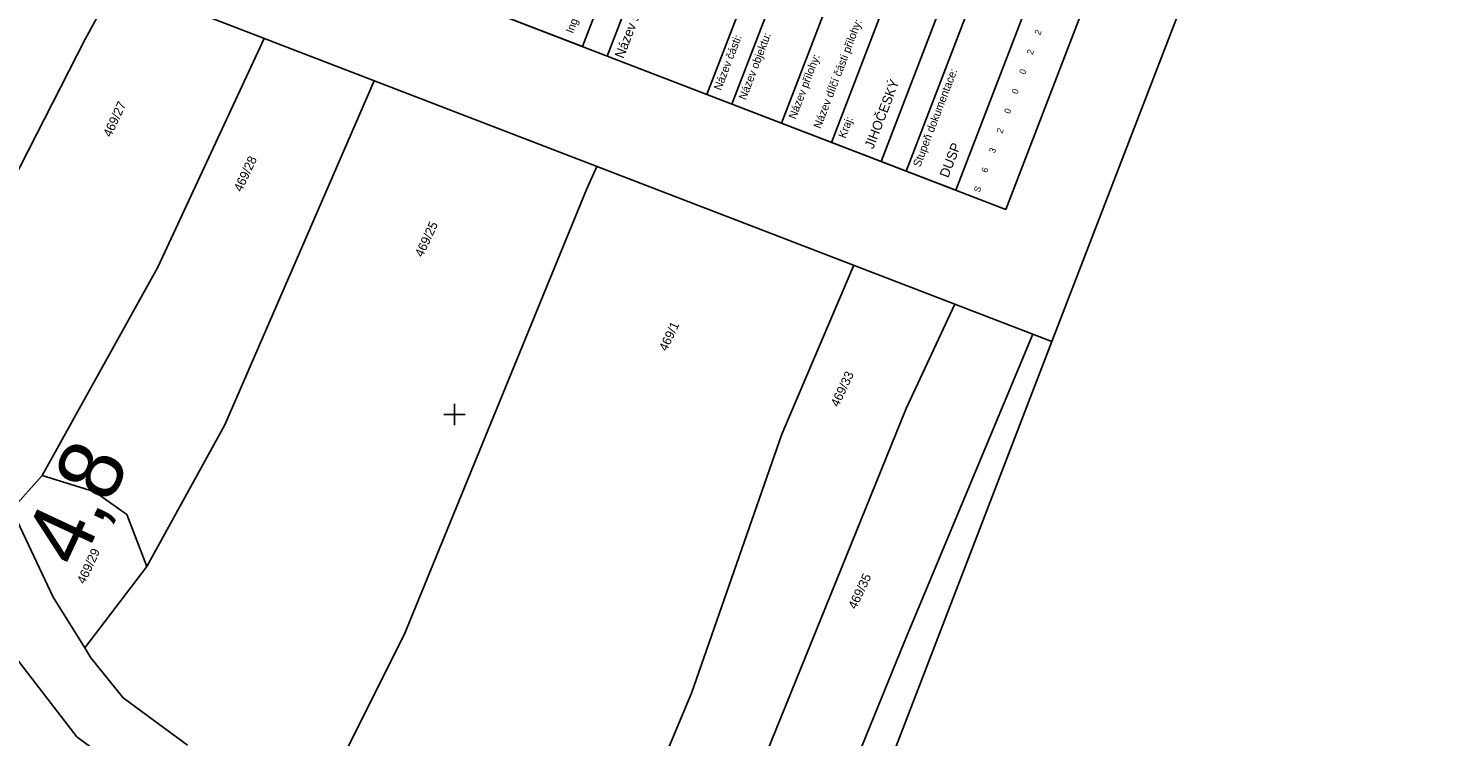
# Model space of a CAD drawing. Extents: x -755344 to -754413, y -1162670 to -1161477.
# Drawn here: x -754679.8 to -754412.6, y -1161960.4 to -1161827.7 of the extents above; entities that cross this region are included whole.
import ezdxf

# ---------------------------------------------------------------- set-up
doc = ezdxf.new("R2010")
doc.units = 0
for name, color, linetype in [('Formát', 7, 'Continuous'), ('Katastrální hranice', 7, 'Continuous'), ('Popisove_pole', 7, 'Continuous'), ('SO 11-10-01_popisove_pole', 7, 'Continuous'), ('Staniceni a namezniky', 7, 'Continuous'), ('Síť', 7, 'Continuous'), ('Vrstva 55', 7, 'Continuous'), ('Vrstva 57', 7, 'Continuous')]:
    doc.layers.add(name, color=color, linetype=linetype)

msp = doc.modelspace()

# ---------------------------------------------------------------- linework, layer by layer
at = {"layer": 'Formát'}
msp.add_line((-754488.01, -1161886.37), (-754412.58, -1161690.39), dxfattribs=at)
msp.add_lwpolyline([(-754488.01, -1161886.37), (-754789.71, -1162670.32), (-755344.08, -1162456.97), (-755042.37, -1161673.02)], close=True, dxfattribs=at)
for points in [[(-755344.08, -1162456.97), (-754789.71, -1162670.32), (-754488.01, -1161886.37), (-755042.37, -1161673.02)], [(-755344.08, -1162456.97), (-754789.71, -1162670.32), (-754488.01, -1161886.37), (-755042.37, -1161673.02)], [(-754789.71, -1162670.32), (-754488.01, -1161886.37), (-755042.37, -1161673.02), (-755344.08, -1162456.97)]]:
    msp.add_lwpolyline(points, dxfattribs=at)
at = {"layer": 'Katastrální hranice'}
msp.add_line((-754682.93, -1161917.84), (-754675.16, -1161934.28), dxfattribs=at)
at = {"layer": 'SO 11-10-01_popisove_pole'}
for p, q in [((-754552.69, -1161840.05), (-754505.87, -1161718.4)), ((-754548.02, -1161841.85), (-754501.2, -1161720.2)), ((-754538.69, -1161845.44), (-754491.87, -1161723.79)), ((-754529.35, -1161849.03), (-754482.54, -1161727.38)), ((-754520.02, -1161852.62), (-754473.2, -1161730.97)), ((-754515.36, -1161854.42), (-754468.54, -1161732.77))]:
    msp.add_line(p, q, dxfattribs=at)
for points in [[(-754739.34, -1161768.22), (-754678.28, -1161609.56), (-754435.63, -1161702.95), (-754496.69, -1161861.6)], [(-754622.68, -1161813.11), (-754561.62, -1161654.46), (-754514.96, -1161672.42), (-754576.02, -1161831.07)], [(-754571.36, -1161832.88), (-754510.3, -1161674.22), (-754444.97, -1161699.37), (-754506.03, -1161858.02)]]:
    msp.add_lwpolyline(points, close=True, dxfattribs=at)
at = {"layer": 'Síť'}
for points in [[(-754600, -1161898), (-754600, -1161900), (-754600, -1161902)], [(-754598, -1161900), (-754600, -1161900), (-754602, -1161900)]]:
    msp.add_lwpolyline(points, dxfattribs=at)
at = {"layer": 'Vrstva 55'}
for p, q in [((-754682.93, -1161917.84), (-754677.24, -1161911.45)), ((-754682.93, -1161917.84), (-754675.16, -1161934.28)), ((-754682.93, -1161917.84), (-754675.16, -1161934.28)), ((-754657.61, -1161928.54), (-754669.27, -1161943.74)), ((-754675.16, -1161934.28), (-754669.27, -1161943.74)), ((-754675.16, -1161934.28), (-754669.27, -1161943.74))]:
    msp.add_line(p, q, dxfattribs=at)
for points in [[(-754700.13, -1161883.31), (-754693.64, -1161874.43), (-754682.9, -1161856.46), (-754669.27, -1161829.84), (-754663.3, -1161818.91)], [(-754677.24, -1161911.45), (-754655.58, -1161872.43), (-754635.62, -1161829.56)], [(-754615.06, -1161837.48), (-754643, -1161901.95), (-754657.61, -1161928.54)], [(-754573.32, -1161853.54), (-754575.25, -1161857.88), (-754609.39, -1161941.34), (-754620.82, -1161964.09), (-754630.9, -1161973.72)], [(-754581.59, -1162005.57), (-754574.99, -1161995.43), (-754567.68, -1161981.15), (-754555.59, -1161952.23), (-754538.63, -1161903.69), (-754525.17, -1161872.07)], [(-754566.03, -1162015.68), (-754549.09, -1161982.12), (-754515.32, -1161898.89), (-754506.22, -1161879.36)], [(-754548.91, -1162026.6), (-754544.92, -1162019.1), (-754539.09, -1162000.11), (-754515.76, -1161942.9), (-754491.63, -1161884.98)], [(-754677.24, -1161911.45), (-754667.41, -1161914.5), (-754661.4, -1161918.76), (-754657.61, -1161928.54)], [(-754637.39, -1161984.8), (-754642.71, -1161981.11), (-754670.75, -1161960.4), (-754682.08, -1161945.77), (-754686.04, -1161937.95)], [(-754669.27, -1161943.74), (-754668.12, -1161945.6), (-754662.1, -1161953.11), (-754649.99, -1161962)], [(-754669.27, -1161943.74), (-754668.12, -1161945.6), (-754662.1, -1161953.11), (-754649.99, -1161962)]]:
    msp.add_lwpolyline(points, dxfattribs=at)

# ---------------------------------------------------------------- texts
at = {"layer": 'Popisove_pole'}
for s, p in [('2', (-754490.24, -1161829.04)), ('2', (-754491.66, -1161832.72)), ('0', (-754493.08, -1161836.41)), ('0', (-754494.5, -1161840.09)), ('0', (-754495.92, -1161843.78)), ('2', (-754497.34, -1161847.47)), ('3', (-754498.76, -1161851.15)), ('6', (-754500.18, -1161854.84)), ('S', (-754501.59, -1161858.53))]:
    msp.add_text(s, height=1.2, rotation=68.9507, dxfattribs=at).set_placement(p)
at = {"layer": 'SO 11-10-01_popisove_pole'}
for s, height, p in [('Ing. Vít Hoznour', 1.5, (-754577.79, -1161828.73)), ('Název stavby/akce:', 1.8, (-754568.33, -1161833.44)), ('Název dílčí části přílohy:', 1.5, (-754531.39, -1161846.59)), ('Název části:', 1.5, (-754550.05, -1161839.41)), ('Název objektu:', 1.5, (-754545.39, -1161841.2)), ('Název přílohy:', 1.5, (-754536.05, -1161844.8)), ('JIHOČESKÝ', 1.8, (-754521.5, -1161850.4)), ('Stupeň dokumentace:', 1.5, (-754512.72, -1161853.77)), ('Kraj:', 1.5, (-754526.72, -1161848.39)), ('DUSP', 1.8, (-754507.46, -1161855.8))]:
    msp.add_text(s, height=height, rotation=68.9507, dxfattribs=at).set_placement(p)
at = {"layer": 'Staniceni a namezniky'}
msp.add_text('4,8', height=12, rotation=64.9752, dxfattribs=at).set_placement((-754670.25, -1161929.14))
at = {"layer": 'Vrstva 57'}
for s, p in [('469/27', (-754664.38, -1161848.18)), ('469/28', (-754639.89, -1161858.42)), ('469/25', (-754605.96, -1161870.67)), ('469/1', (-754560.21, -1161888.31)), ('469/33', (-754528.03, -1161898.74)), ('469/29', (-754669.29, -1161931.93)), ('469/35', (-754524.75, -1161936.65))]:
    msp.add_text(s, height=1.7, rotation=65, dxfattribs=at).set_placement(p)

doc.saveas('drawing.dxf')
